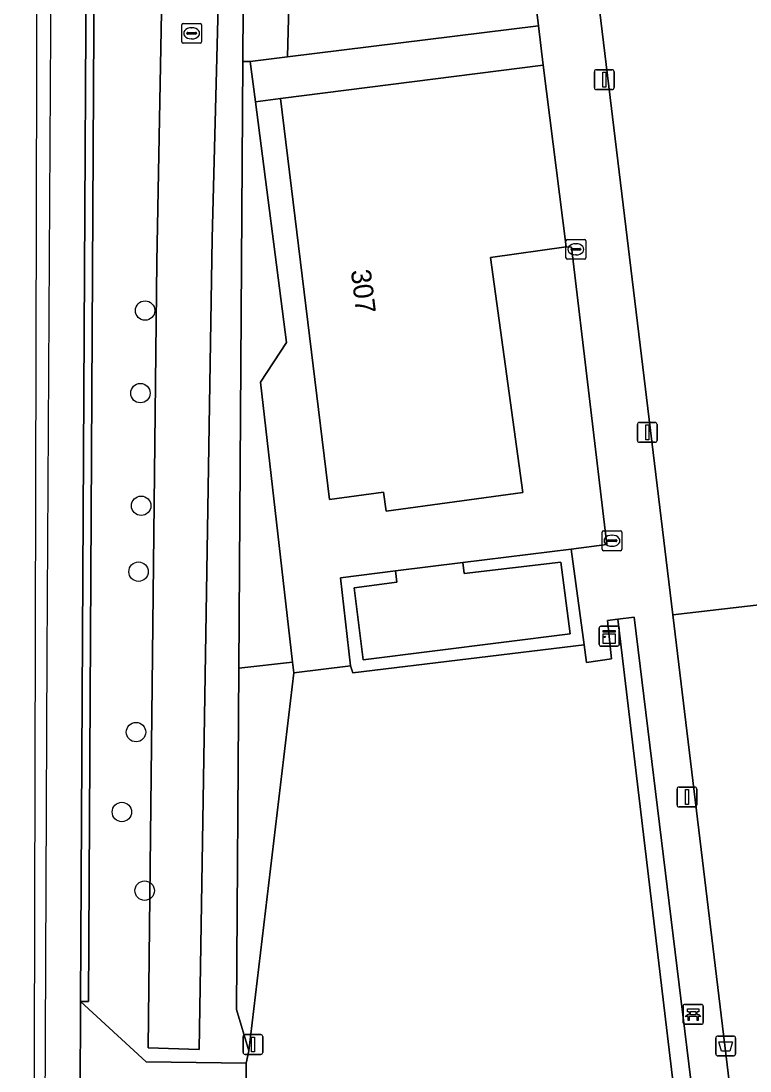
# Model space of a CAD drawing. Extents: x 162156 to 163172, y 378995 to 380779.
# Drawn here: x 162162 to 162198.7, y 380033.7 to 380086.5 of the extents above; entities that cross this region are included whole.
import ezdxf

# ---------------------------------------------------------------- set-up
doc = ezdxf.new("R2010")
doc.units = 0
for name, color, linetype in [('IMGEO_Afvalbak', 7, 'Continuous'), ('IMGEO_Bank', 7, 'Continuous'), ('IMGEO_Berm_open', 7, 'Continuous'), ('IMGEO_Boom', 7, 'Continuous'), ('IMGEO_Groenvoorziening', 7, 'Continuous'), ('IMGEO_Haag', 7, 'Continuous'), ('IMGEO_Hek', 7, 'Continuous'), ('IMGEO_Kast', 7, 'Continuous'), ('IMGEO_Kolk', 7, 'Continuous'), ('IMGEO_Lichtmast', 7, 'Continuous'), ('IMGEO_Pand', 7, 'Continuous'), ('IMGEO_Pand_nummerreeks', 7, 'Continuous'), ('IMGEO_Parkeervlak_gesloten', 7, 'Continuous'), ('IMGEO_Rijbaan_lokaal_gesloten', 7, 'Continuous'), ('IMGEO_Rijbaan_lokaal_open', 7, 'Continuous'), ('IMGEO_Rioolput', 7, 'Continuous'), ('IMGEO_Terreindeel_halfverhard', 7, 'Continuous'), ('IMGEO_Verkeerseiland_open', 7, 'Continuous'), ('IMGEO_Voetpad_halfverhard', 7, 'Continuous'), ('IMGEO_Voetpad_open', 7, 'Continuous'), ('IMGEO_Waterloop', 7, 'Continuous')]:
    doc.layers.add(name, color=color, linetype=linetype)

msp = doc.modelspace()

# ---------------------------------------------------------------- linework, layer by layer
at = {"layer": 'IMGEO_Afvalbak'}
for p, q in [((162196.988, 380034.521), (162196.988, 380035.321)), ((162196.988, 380035.321), (162196.988, 380034.521)), ((162197.088, 380035.421), (162197.878, 380035.421)), ((162197.878, 380035.421), (162197.088, 380035.421)), ((162197.978, 380035.321), (162197.978, 380034.521)), ((162197.978, 380034.521), (162197.978, 380035.321)), ((162197.878, 380034.421), (162197.088, 380034.421)), ((162197.088, 380034.421), (162197.878, 380034.421))]:
    msp.add_line(p, q, dxfattribs=at)
msp.add_lwpolyline([(162197.131, 380035.135), (162197.835, 380035.135), (162197.686, 380034.665), (162197.28, 380034.665), (162197.131, 380035.135)], dxfattribs=at)
for centre, start, end in [((162197.088, 380035.321), 90, 180), ((162197.088, 380035.321), 90, 180), ((162197.878, 380035.321), 0, 90), ((162197.878, 380035.321), 360, 90), ((162197.088, 380034.521), 180, 270), ((162197.088, 380034.521), 180, 270), ((162197.878, 380034.521), 270, 0), ((162197.878, 380034.521), 270, 0)]:
    msp.add_arc(centre, 0.1, start, end, dxfattribs=at)
at = {"layer": 'IMGEO_Bank'}
for p, q in [((162195.347, 380036.089), (162195.347, 380036.93)), ((162195.347, 380036.93), (162195.347, 380036.089)), ((162195.422, 380037.014), (162196.263, 380037.014)), ((162196.263, 380037.014), (162195.422, 380037.014)), ((162195.656, 380036.52), (162195.656, 380036.626)), ((162195.7, 380036.626), (162195.7, 380036.52)), ((162195.988, 380036.632), (162195.706, 380036.632)), ((162195.994, 380036.52), (162195.994, 380036.626)), ((162196.038, 380036.626), (162196.038, 380036.52)), ((162196.347, 380036.939), (162196.347, 380036.098)), ((162196.347, 380036.098), (162196.347, 380036.939)), ((162196.272, 380036.014), (162195.431, 380036.014)), ((162195.431, 380036.014), (162196.272, 380036.014)), ((162196.044, 380036.412), (162195.651, 380036.412)), ((162195.706, 380036.514), (162195.988, 380036.514))]:
    msp.add_line(p, q, dxfattribs=at)
for points in [[(162195.65, 380036.632), (162195.564, 380036.632), (162195.564, 380036.793), (162196.127, 380036.793), (162196.127, 380036.632), (162196.044, 380036.632)], [(162195.594, 380036.412), (162195.452, 380036.412), (162195.564, 380036.514), (162195.65, 380036.514)], [(162195.644, 380036.405), (162195.644, 380036.198), (162195.601, 380036.198), (162195.601, 380036.405)], [(162196.044, 380036.514), (162196.127, 380036.514), (162196.239, 380036.412), (162196.1, 380036.412)], [(162196.094, 380036.405), (162196.094, 380036.198), (162196.05, 380036.198), (162196.05, 380036.405)]]:
    msp.add_lwpolyline(points, dxfattribs=at)
for centre, radius, start, end in [((162195.425, 380036.936), 0.0779, 92.4484, 184.2845), ((162195.425, 380036.936), 0.0779, 92.4484, 184.2845), ((162195.649, 380036.625), 0.00671, 2.8957, 87.1043), ((162195.706, 380036.625), 0.00671, 92.8957, 177.1043), ((162195.988, 380036.625), 0.00671, 2.8957, 87.1043), ((162196.045, 380036.625), 0.00671, 92.8957, 177.1043), ((162196.269, 380036.936), 0.0779, 2.4484, 94.2845), ((162196.269, 380036.936), 0.0779, 2.4484, 94.2845), ((162195.425, 380036.092), 0.0779, 182.4484, 274.2845), ((162195.425, 380036.092), 0.0779, 182.4484, 274.2845), ((162195.594, 380036.405), 0.00671, 2.8957, 87.1043), ((162195.651, 380036.405), 0.00671, 92.8957, 177.1043), ((162195.649, 380036.521), 0.00671, 272.8957, 357.1043), ((162195.706, 380036.521), 0.00671, 182.8957, 267.1043), ((162195.988, 380036.521), 0.00671, 272.8957, 357.1043), ((162196.045, 380036.521), 0.00671, 182.8957, 267.1043), ((162196.043, 380036.405), 0.00671, 2.8957, 87.1043), ((162196.1, 380036.405), 0.00671, 92.8957, 177.1043), ((162196.269, 380036.092), 0.0779, 272.4484, 4.2845), ((162196.269, 380036.092), 0.0779, 272.4484, 4.2845)]:
    msp.add_arc(centre, radius, start, end, dxfattribs=at)
at = {"layer": 'IMGEO_Berm_open'}
msp.add_lwpolyline([(162165.864, 380125.971), (162165.486, 380125.971), (162164.999, 380037.164), (162165.398, 380037.16), (162165.869, 380122.903)], close=True, dxfattribs=at)
at = {"layer": 'IMGEO_Boom'}
for centre in [(162168.252, 380071.95), (162168.016, 380067.792), (162168.055, 380062.121), (162167.922, 380058.802), (162167.797, 380050.724), (162167.083, 380046.704), (162168.231, 380042.741)]:
    msp.add_circle(centre, 0.489, dxfattribs=at)
at = {"layer": 'IMGEO_Groenvoorziening'}
for points in [[(162173.483, 380034.68), (162172.851, 380036.76), (162172.964, 380053.937), (162173.166, 380084.491), (162173.347, 380112.055), (162173.446, 380127.084), (162173.468, 380130.371), (162173.679, 380134.692), (162173.698, 380135.083), (162172.984, 380134.992), (162172.447, 380107.456), (162171.631, 380075.578), (162170.967, 380034.746), (162168.408, 380034.827), (162168.85, 380074.41), (162169.945, 380133.695)], [(162169.948, 380134.611), (162165.748, 380134.086), (162165.486, 380125.971), (162165.864, 380125.971), (162165.869, 380122.903), (162165.398, 380037.16), (162164.999, 380037.164), (162168.308, 380034.127), (162173.34, 380034.054), (162173.483, 380034.68)]]:
    msp.add_lwpolyline(points, dxfattribs=at)
for points in [[(162183.103, 380125.164), (162182.795, 380125.12), (162184.349, 380113.156), (162177.11, 380112.354), (162176.146, 380112.277), (162176.15, 380112.24), (162175.426, 380084.724), (162188.063, 380086.289), (162187.478, 380091.097), (162187.277, 380091.068)], [(162176.15, 380112.24), (162176.146, 380112.277), (162173.347, 380112.055), (162173.166, 380084.491), (162173.547, 380084.491), (162175.426, 380084.724)], [(162173.547, 380084.491), (162173.166, 380084.491), (162172.964, 380053.937), (162175.675, 380054.248), (162174.056, 380068.346), (162175.366, 380070.343), (162173.807, 380082.466)], [(162178.084, 380058.488), (162178.59, 380054.063), (162178.714, 380053.711), (162190.361, 380055.115), (162189.701, 380059.943), (162184.25, 380059.262), (162184.325, 380058.71), (162189.19, 380059.283), (162189.649, 380055.678), (162179.235, 380054.366), (162178.787, 380057.988), (162180.928, 380058.279), (162180.852, 380058.838)], [(162196.797, 380024.421), (162192.874, 380056.505), (162192.047, 380056.41), (162195.887, 380024.305)], [(162175.748, 380053.703), (162175.738, 380053.702), (162175.675, 380054.248), (162172.964, 380053.937), (162172.851, 380036.76), (162173.483, 380034.68)]]:
    msp.add_lwpolyline(points, close=True, dxfattribs=at)
at = {"layer": 'IMGEO_Haag'}
for points in [[(162178.084, 380058.488), (162178.59, 380054.063), (162178.714, 380053.711), (162190.361, 380055.115), (162189.701, 380059.943), (162184.25, 380059.262), (162184.325, 380058.71), (162189.19, 380059.283), (162189.649, 380055.678), (162179.235, 380054.366), (162178.787, 380057.988), (162180.928, 380058.279), (162180.852, 380058.838)], [(162196.797, 380024.421), (162192.874, 380056.505), (162192.047, 380056.41), (162195.887, 380024.305)]]:
    msp.add_lwpolyline(points, close=True, dxfattribs=at)
at = {"layer": 'IMGEO_Hek'}
for points in [[(162173.347, 380112.055), (162173.166, 380084.491)], [(162173.166, 380084.491), (162172.964, 380053.937)], [(162194.822, 380056.632), (162228.937, 380060.599)], [(162172.964, 380053.937), (162172.851, 380036.76), (162173.483, 380034.68)], [(162173.483, 380034.68), (162173.34, 380034.054)]]:
    msp.add_lwpolyline(points, dxfattribs=at)
at = {"layer": 'IMGEO_Kast'}
for p, q in [((162191.119, 380055.131), (162191.119, 380055.972)), ((162191.119, 380055.972), (162191.119, 380055.131)), ((162191.194, 380056.056), (162192.035, 380056.056)), ((162192.035, 380056.056), (162191.194, 380056.056)), ((162192.119, 380055.981), (162192.119, 380055.14)), ((162192.119, 380055.14), (162192.119, 380055.981)), ((162192.044, 380055.056), (162191.203, 380055.056)), ((162191.203, 380055.056), (162192.044, 380055.056))]:
    msp.add_line(p, q, dxfattribs=at)
for points in [[(162191.314, 380055.846), (162191.914, 380055.846), (162191.914, 380055.761), (162191.314, 380055.761), (162191.314, 380055.846)], [(162191.314, 380055.671), (162191.914, 380055.671), (162191.914, 380055.182), (162191.314, 380055.182), (162191.314, 380055.671)]]:
    msp.add_lwpolyline(points, dxfattribs=at)
msp.add_circle((162191.398, 380055.52), 0.0377, dxfattribs=at)
for centre, start, end in [((162191.197, 380055.978), 92.4484, 184.2845), ((162191.197, 380055.978), 92.4484, 184.2845), ((162192.041, 380055.978), 2.4484, 94.2845), ((162192.041, 380055.978), 2.4484, 94.2845), ((162191.197, 380055.134), 182.4484, 274.2845), ((162191.197, 380055.134), 182.4484, 274.2845), ((162192.041, 380055.134), 272.4484, 4.2845), ((162192.041, 380055.134), 272.4484, 4.2845)]:
    msp.add_arc(centre, 0.0779, start, end, dxfattribs=at)
at = {"layer": 'IMGEO_Kolk'}
for p, q in [((162189.441, 380074.609), (162189.441, 380075.461)), ((162189.516, 380075.535), (162190.368, 380075.535)), ((162189.929, 380075.315), (162189.954, 380075.315)), ((162190.442, 380075.461), (162190.442, 380074.609)), ((162189.7, 380075.029), (162189.7, 380075.041)), ((162190.138, 380074.992), (162189.74, 380074.992)), ((162189.743, 380075.078), (162190.141, 380075.078)), ((162189.952, 380074.755), (162189.927, 380074.755)), ((162190.184, 380075.041), (162190.184, 380075.029)), ((162190.368, 380074.535), (162189.516, 380074.535)), ((162191.334, 380060.86), (162192.186, 380060.86)), ((162191.259, 380059.934), (162191.259, 380060.786)), ((162191.518, 380060.354), (162191.518, 380060.366)), ((162191.956, 380060.317), (162191.558, 380060.317)), ((162191.561, 380060.403), (162191.959, 380060.403)), ((162191.747, 380060.64), (162191.772, 380060.64)), ((162192.002, 380060.366), (162192.002, 380060.354)), ((162192.26, 380060.786), (162192.26, 380059.934)), ((162192.186, 380059.86), (162191.334, 380059.86)), ((162191.77, 380060.08), (162191.745, 380060.08))]:
    msp.add_line(p, q, dxfattribs=at)
for points in [[(162189.441, 380074.609), (162189.441, 380075.461)], [(162189.516, 380075.535), (162190.368, 380075.535)], [(162190.442, 380075.461), (162190.442, 380074.609)], [(162190.368, 380074.535), (162189.516, 380074.535)], [(162191.334, 380060.86), (162192.186, 380060.86)], [(162191.259, 380059.934), (162191.259, 380060.786)], [(162192.26, 380060.786), (162192.26, 380059.934)], [(162192.186, 380059.86), (162191.334, 380059.86)]]:
    msp.add_lwpolyline(points, dxfattribs=at)
for centre, radius, start, end in [((162189.518, 380075.459), 0.0765, 91.552, 178.448), ((162189.518, 380075.459), 0.0765, 91.552, 178.448), ((162190.366, 380075.459), 0.0765, 1.552, 88.448), ((162190.366, 380075.459), 0.0765, 1.552, 88.448), ((162189.518, 380074.611), 0.0765, 181.552, 268.448), ((162189.518, 380074.611), 0.0765, 181.552, 268.448), ((162189.74, 380075.038), 0.0403, 85.8775, 175.7526), ((162189.737, 380075.028), 0.0366, 178.938, 274.7102), ((162190.141, 380075.035), 0.043, 264.8664, 352.4533), ((162190.145, 380075.04), 0.0386, 1.7309, 96.639), ((162190.366, 380074.611), 0.0765, 271.552, 358.448), ((162190.366, 380074.611), 0.0765, 271.552, 358.448), ((162191.336, 380060.784), 0.0765, 91.552, 178.448), ((162191.336, 380060.784), 0.0765, 91.552, 178.448), ((162192.184, 380060.784), 0.0765, 1.552, 88.448), ((162192.184, 380060.784), 0.0765, 1.552, 88.448), ((162191.558, 380060.363), 0.0403, 85.8775, 175.7526), ((162191.555, 380060.353), 0.0366, 178.938, 274.7102), ((162191.959, 380060.36), 0.043, 264.8664, 352.4533), ((162191.963, 380060.365), 0.0386, 1.7309, 96.639), ((162191.336, 380059.936), 0.0765, 181.552, 268.448), ((162191.336, 380059.936), 0.0765, 181.552, 268.448), ((162192.184, 380059.936), 0.0765, 271.552, 358.448), ((162192.184, 380059.936), 0.0765, 271.552, 358.448)]:
    msp.add_arc(centre, radius, start, end, dxfattribs=at)
for centre, major_axis, ratio, start_param, end_param in [((162189.928, 380075.035), (-0.387, 0.002), 0.722429, 4.712389, 7.853982), ((162189.953, 380075.035), (-0.39, 0.002), 0.717154, 1.570796, 4.712389), ((162191.746, 380060.36), (-0.387, 0.002), 0.722429, 4.712389, 7.853982), ((162191.771, 380060.36), (-0.39, 0.002), 0.717154, 1.570796, 4.712389)]:
    msp.add_ellipse(centre, major_axis=major_axis, ratio=ratio, start_param=start_param, end_param=end_param, dxfattribs=at)
at = {"layer": 'IMGEO_Lichtmast'}
for p, q in [((162190.873, 380083.177), (162190.873, 380083.977)), ((162190.873, 380083.977), (162190.873, 380083.177)), ((162190.973, 380084.077), (162191.763, 380084.077)), ((162191.763, 380084.077), (162190.973, 380084.077)), ((162191.863, 380083.977), (162191.863, 380083.177)), ((162191.863, 380083.177), (162191.863, 380083.977)), ((162191.763, 380083.077), (162190.973, 380083.077)), ((162190.973, 380083.077), (162191.763, 380083.077)), ((162193.038, 380065.416), (162193.038, 380066.216)), ((162193.038, 380066.216), (162193.038, 380065.416)), ((162193.138, 380066.316), (162193.928, 380066.316)), ((162193.928, 380066.316), (162193.138, 380066.316)), ((162194.028, 380066.216), (162194.028, 380065.416)), ((162194.028, 380065.416), (162194.028, 380066.216)), ((162193.928, 380065.316), (162193.138, 380065.316)), ((162193.138, 380065.316), (162193.928, 380065.316)), ((162195.035, 380047.057), (162195.035, 380047.857)), ((162195.035, 380047.857), (162195.035, 380047.057)), ((162195.135, 380047.957), (162195.925, 380047.957)), ((162195.925, 380047.957), (162195.135, 380047.957)), ((162196.025, 380047.857), (162196.025, 380047.057)), ((162196.025, 380047.057), (162196.025, 380047.857)), ((162195.925, 380046.957), (162195.135, 380046.957)), ((162195.135, 380046.957), (162195.925, 380046.957)), ((162173.288, 380035.494), (162174.078, 380035.494)), ((162174.078, 380035.494), (162173.288, 380035.494)), ((162173.188, 380034.594), (162173.188, 380035.394)), ((162173.188, 380035.394), (162173.188, 380034.594)), ((162174.178, 380035.394), (162174.178, 380034.594)), ((162174.178, 380034.594), (162174.178, 380035.394)), ((162174.078, 380034.494), (162173.288, 380034.494)), ((162173.288, 380034.494), (162174.078, 380034.494))]:
    msp.add_line(p, q, dxfattribs=at)
for points in [[(162191.293, 380083.952), (162191.443, 380083.952), (162191.443, 380083.202), (162191.293, 380083.202), (162191.293, 380083.952)], [(162193.458, 380066.191), (162193.608, 380066.191), (162193.608, 380065.441), (162193.458, 380065.441), (162193.458, 380066.191)], [(162195.455, 380047.832), (162195.605, 380047.832), (162195.605, 380047.082), (162195.455, 380047.082), (162195.455, 380047.832)], [(162173.608, 380035.369), (162173.758, 380035.369), (162173.758, 380034.619), (162173.608, 380034.619), (162173.608, 380035.369)]]:
    msp.add_lwpolyline(points, dxfattribs=at)
for centre, start, end in [((162190.973, 380083.977), 90, 180), ((162190.973, 380083.977), 90, 180), ((162191.763, 380083.977), 0, 90), ((162191.763, 380083.977), 360, 90), ((162190.973, 380083.177), 180, 270), ((162190.973, 380083.177), 180, 270), ((162191.763, 380083.177), 270, 0), ((162191.763, 380083.177), 270, 0), ((162193.138, 380066.216), 90, 180), ((162193.138, 380066.216), 90, 180), ((162193.928, 380066.216), 0, 90), ((162193.928, 380066.216), 360, 90), ((162193.138, 380065.416), 180, 270), ((162193.138, 380065.416), 180, 270), ((162193.928, 380065.416), 270, 0), ((162193.928, 380065.416), 270, 0), ((162195.135, 380047.857), 90, 180), ((162195.135, 380047.857), 90, 180), ((162195.925, 380047.857), 0, 90), ((162195.925, 380047.857), 360, 90), ((162195.135, 380047.057), 180, 270), ((162195.135, 380047.057), 180, 270), ((162195.925, 380047.057), 270, 0), ((162195.925, 380047.057), 270, 0), ((162173.288, 380035.394), 90, 180), ((162173.288, 380035.394), 90, 180), ((162174.078, 380035.394), 0, 90), ((162174.078, 380035.394), 360, 90), ((162173.288, 380034.594), 180, 270), ((162173.288, 380034.594), 180, 270), ((162174.078, 380034.594), 270, 0), ((162174.078, 380034.594), 270, 0)]:
    msp.add_arc(centre, 0.1, start, end, dxfattribs=at)
at = {"layer": 'IMGEO_Pand'}
msp.add_lwpolyline([(162175.064, 380082.628), (162177.542, 380062.436), (162180.256, 380062.809), (162180.389, 380061.848), (162187.274, 380062.794), (162185.648, 380074.627), (162189.457, 380075.151), (162188.303, 380084.312)], close=True, dxfattribs=at)
at = {"layer": 'IMGEO_Parkeervlak_gesloten'}
msp.add_lwpolyline([(162192.047, 380056.41), (162191.538, 380056.351), (162191.737, 380054.409), (162190.483, 380054.224), (162190.361, 380055.115), (162178.714, 380053.711), (162178.59, 380054.063), (162175.748, 380053.703), (162173.483, 380034.68), (162173.34, 380034.054), (162173.295, 380028.997), (162173.455, 380028.431), (162173.572, 380028.43), (162173.476, 380015.701), (162173.259, 380015.657), (162173.418, 380015.013), (162174.046, 380015.035), (162174.044, 380015.347), (162186.163, 380016.889), (162186.126, 380017.197), (162186.027, 380018.304), (162193.872, 380019.23), (162193.3, 380023.977), (162195.887, 380024.305)], close=True, dxfattribs=at)
at = {"layer": 'IMGEO_Rijbaan_lokaal_gesloten'}
msp.add_lwpolyline([(162164.965, 380027.627), (162164.999, 380037.164), (162165.486, 380125.971), (162163.727, 380125.983), (162163.305, 380054.64), (162163.185, 380027.629)], close=True, dxfattribs=at)
at = {"layer": 'IMGEO_Rijbaan_lokaal_open'}
msp.add_lwpolyline([(162173.34, 380034.054), (162168.308, 380034.127), (162164.999, 380037.164), (162164.965, 380027.627), (162164.961, 380026.513), (162168.254, 380029.074), (162173.295, 380028.997)], close=True, dxfattribs=at)
at = {"layer": 'IMGEO_Rioolput'}
for p, q in [((162170.095, 380085.485), (162170.095, 380086.337)), ((162170.17, 380086.411), (162171.022, 380086.411)), ((162171.096, 380086.337), (162171.096, 380085.485)), ((162170.354, 380085.905), (162170.354, 380085.917)), ((162170.792, 380085.868), (162170.394, 380085.868)), ((162170.397, 380085.954), (162170.795, 380085.954)), ((162170.583, 380086.191), (162170.608, 380086.191)), ((162170.838, 380085.917), (162170.838, 380085.905)), ((162171.022, 380085.411), (162170.17, 380085.411)), ((162170.606, 380085.631), (162170.581, 380085.631))]:
    msp.add_line(p, q, dxfattribs=at)
for points in [[(162170.095, 380085.485), (162170.095, 380086.337)], [(162170.17, 380086.411), (162171.022, 380086.411)], [(162171.096, 380086.337), (162171.096, 380085.485)], [(162171.022, 380085.411), (162170.17, 380085.411)]]:
    msp.add_lwpolyline(points, dxfattribs=at)
for centre, radius, start, end in [((162170.172, 380086.335), 0.0765, 91.552, 178.448), ((162170.172, 380086.335), 0.0765, 91.552, 178.448), ((162171.02, 380086.335), 0.0765, 1.552, 88.448), ((162171.02, 380086.335), 0.0765, 1.552, 88.448), ((162170.394, 380085.914), 0.0403, 85.8775, 175.7526), ((162170.391, 380085.904), 0.0366, 178.938, 274.7102), ((162170.795, 380085.911), 0.043, 264.8664, 352.4533), ((162170.799, 380085.916), 0.0386, 1.7309, 96.639), ((162170.172, 380085.487), 0.0765, 181.552, 268.448), ((162170.172, 380085.487), 0.0765, 181.552, 268.448), ((162171.02, 380085.487), 0.0765, 271.552, 358.448), ((162171.02, 380085.487), 0.0765, 271.552, 358.448)]:
    msp.add_arc(centre, radius, start, end, dxfattribs=at)
for centre, major_axis, ratio, start_param, end_param in [((162170.582, 380085.911), (-0.387, 0.002), 0.722429, 4.712389, 7.853982), ((162170.607, 380085.911), (-0.39, 0.002), 0.717154, 1.570796, 4.712389)]:
    msp.add_ellipse(centre, major_axis=major_axis, ratio=ratio, start_param=start_param, end_param=end_param, dxfattribs=at)
at = {"layer": 'IMGEO_Terreindeel_halfverhard'}
for points in [[(162224.487, 380097.136), (162190.413, 380093.089), (162194.822, 380056.632), (162228.937, 380060.599)], [(162228.937, 380060.599), (162194.822, 380056.632), (162199.226, 380020.209), (162233.359, 380024.296)]]:
    msp.add_lwpolyline(points, close=True, dxfattribs=at)
at = {"layer": 'IMGEO_Verkeerseiland_open'}
msp.add_lwpolyline([(162162.092, 379824.682), (162162.005, 379825.114), (162162.447, 379935.336), (162162.868, 380112.498), (162163.394, 380125.989), (162163.727, 380125.983), (162163.305, 380054.64), (162163.185, 380027.629), (162162.452, 379863.521), (162162.462, 379831.9)], dxfattribs=at)
at = {"layer": 'IMGEO_Voetpad_halfverhard'}
msp.add_lwpolyline([(162184.25, 380059.262), (162180.852, 380058.838), (162180.928, 380058.279), (162178.787, 380057.988), (162179.235, 380054.366), (162189.649, 380055.678), (162189.19, 380059.283), (162184.325, 380058.71)], close=True, dxfattribs=at)
at = {"layer": 'IMGEO_Voetpad_open'}
msp.add_lwpolyline([(162235.016, 380023.417), (162221.449, 380134.839), (162185.987, 380130.642), (162185.525, 380134.22), (162183.241, 380133.942), (162184.026, 380127.5), (162188.435, 380091.313), (162187.47, 380091.163), (162187.478, 380091.097), (162188.063, 380086.289), (162188.303, 380084.312), (162189.457, 380075.151), (162189.718, 380075.138), (162191.492, 380060.166), (162189.701, 380059.943), (162190.361, 380055.115), (162190.483, 380054.224), (162191.737, 380054.409), (162191.538, 380056.351), (162192.047, 380056.41), (162192.874, 380056.505), (162196.797, 380024.421)], dxfattribs=at)
for points in [[(162224.487, 380097.136), (162228.937, 380060.599), (162233.359, 380024.296), (162199.226, 380020.209), (162194.822, 380056.632), (162190.413, 380093.089), (162186.006, 380129.538), (162220.05, 380133.559)], [(162188.303, 380084.312), (162188.063, 380086.289), (162175.426, 380084.724), (162173.547, 380084.491), (162173.807, 380082.466), (162175.064, 380082.628)], [(162189.718, 380075.138), (162189.457, 380075.151), (162185.648, 380074.627), (162187.274, 380062.794), (162180.389, 380061.848), (162180.256, 380062.809), (162177.542, 380062.436), (162175.064, 380082.628), (162173.807, 380082.466), (162175.366, 380070.343), (162174.056, 380068.346), (162175.675, 380054.248), (162175.738, 380053.702), (162175.748, 380053.703), (162178.59, 380054.063), (162178.084, 380058.488), (162180.852, 380058.838), (162184.25, 380059.262), (162189.701, 380059.943), (162191.492, 380060.166)]]:
    msp.add_lwpolyline(points, close=True, dxfattribs=at)
at = {"layer": 'IMGEO_Waterloop'}
for points in [[(162171.631, 380075.578), (162172.447, 380107.456), (162172.984, 380134.992), (162172.458, 380134.925), (162169.948, 380134.611)], [(162169.945, 380133.695), (162168.85, 380074.41), (162168.408, 380034.827), (162170.967, 380034.746), (162171.631, 380075.578)]]:
    msp.add_lwpolyline(points, dxfattribs=at)

# ---------------------------------------------------------------- texts
at = {"layer": 'IMGEO_Pand_nummerreeks'}
msp.add_text('307', height=1, rotation=277.1229, dxfattribs=at).set_placement((162178.609, 380073.966))

doc.saveas('drawing.dxf')
